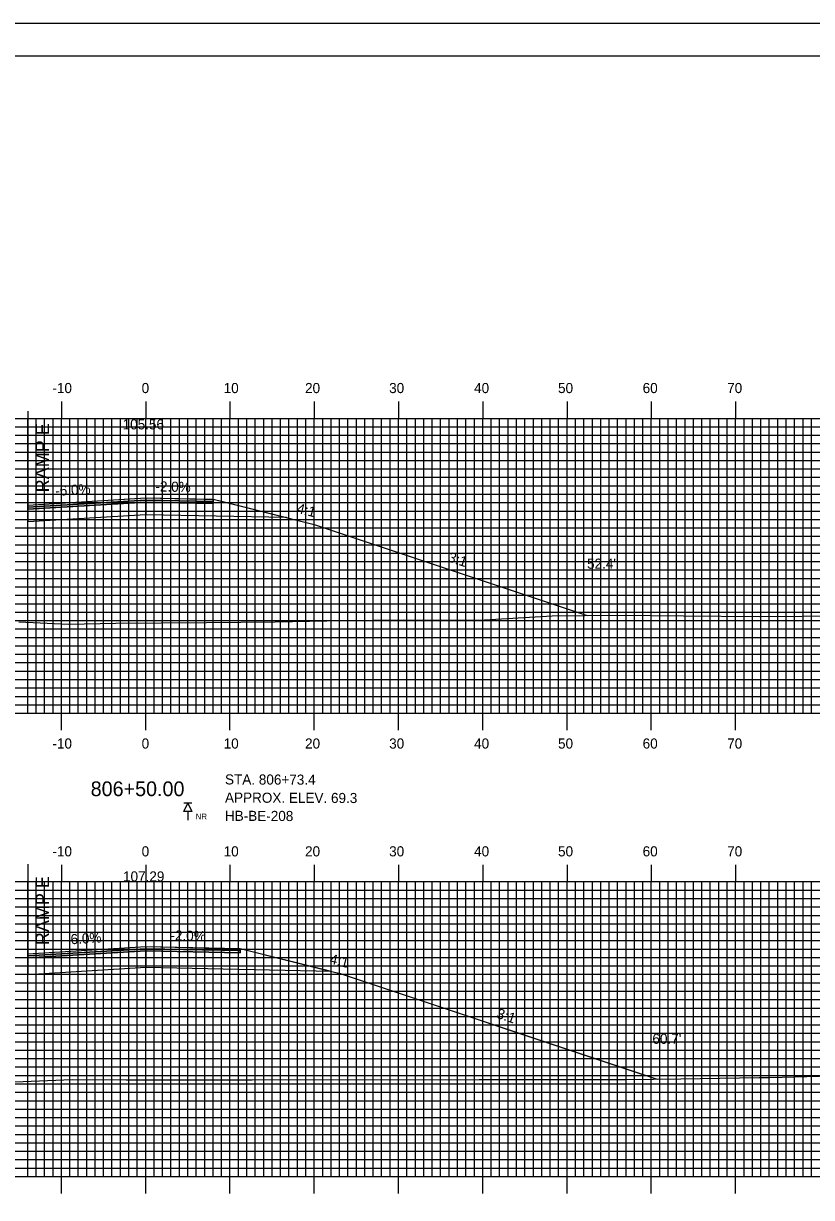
# Model space of a CAD drawing. Extents: x 879 to 1222, y -1658 to -1438.
# Drawn here: x 1030.1 to 1123.7, y -1577.1 to -1437.7 of the extents above; entities that cross this region are included whole.
import ezdxf

# ---------------------------------------------------------------- set-up
doc = ezdxf.new("R2010")
doc.units = 0
for name, color, linetype in [('ANNOTATION', 7, 'Continuous'), ('BORDER', 7, 'Continuous'), ('BORING - NO REFUSAL', 7, 'Continuous'), ('D_Roadway_Centerline', 7, 'Continuous'), ('D_Roadway_Centerline_Text', 7, 'Continuous'), ('D_Roadway_Edge_Shoulder', 7, 'Continuous'), ('D_Roadway_Edge_TW', 7, 'Continuous'), ('D_Roadway_Pavement', 7, 'Continuous'), ('D_Roadway_SlopeLines', 7, 'Continuous'), ('D_Roadway_SubGrade', 7, 'Continuous'), ('D_Text_Standard', 7, 'Continuous'), ('Default', 7, 'Continuous'), ('H_V ANNOTATION', 7, 'Continuous'), ('MAJOR', 7, 'Continuous'), ('MINOR', 7, 'Continuous'), ('PLOT BOUNDARY', 7, 'Continuous'), ('S_Roadway_Centerline', 7, 'Continuous')]:
    doc.layers.add(name, color=color, linetype=linetype)

msp = doc.modelspace()

# ---------------------------------------------------------------- linework, layer by layer
at = {"layer": 'BORDER'}
msp.add_lwpolyline([(895.05, -1651.6), (1215.05, -1651.6), (1215.05, -1441.6), (895.05, -1441.6)], close=True, dxfattribs=at)
at = {"layer": 'BORING - NO REFUSAL'}
for p, q in [((1050.13, -1530.3), (1049.17, -1530.3)), ((1049.65, -1531.26), (1049.65, -1532.32))]:
    msp.add_line(p, q, dxfattribs=at)
msp.add_lwpolyline([(1049.65, -1530.3), (1050.13, -1531.26), (1049.17, -1531.26)], close=True, dxfattribs=at)
at = {"layer": 'D_Roadway_Centerline'}
for points in [[(1030.65, -1494.89), (1042.71, -1494.16), (1044.65, -1494.05), (1051.56, -1494.18), (1052.65, -1494.21), (1053.79, -1494.49), (1061.34, -1496.38), (1061.78, -1496.49), (1064.65, -1497.21), (1068.66, -1498.54), (1097.02, -1508)], [(1030.65, -1548.15), (1044.65, -1547.31), (1055.12, -1547.52), (1055.84, -1547.54), (1066.02, -1550.08), (1066.7, -1550.25), (1067.77, -1550.52), (1067.84, -1550.54), (1102.83, -1562.2), (1105.36, -1563.04)]]:
    msp.add_lwpolyline(points, dxfattribs=at)
at = {"layer": 'D_Roadway_Edge_Shoulder'}
for points in [[(1044.65, -1494.05), (1052.65, -1494.21), (1052.65, -1494.46), (1044.65, -1494.3)], [(1044.65, -1547.31), (1055.84, -1547.54), (1055.84, -1547.79), (1044.65, -1547.56)]]:
    msp.add_lwpolyline(points, close=True, dxfattribs=at)
at = {"layer": 'D_Roadway_Edge_TW'}
for points in [[(1030.65, -1494.89), (1044.65, -1494.05), (1044.65, -1494.3), (1030.65, -1495.14)], [(1030.65, -1548.15), (1044.65, -1547.31), (1044.65, -1547.56), (1030.65, -1548.4)]]:
    msp.add_lwpolyline(points, close=True, dxfattribs=at)
at = {"layer": 'D_Roadway_Pavement'}
for points in [[(1030.65, -1495.14), (1044.65, -1494.3), (1044.65, -1494.55), (1030.65, -1495.39)], [(1044.65, -1494.3), (1052.65, -1494.46), (1052.65, -1494.71), (1044.65, -1494.55)], [(1030.65, -1548.4), (1044.65, -1547.56), (1044.65, -1547.81), (1030.65, -1548.65)], [(1044.65, -1547.56), (1055.84, -1547.79), (1055.84, -1548.04), (1044.65, -1547.81)]]:
    msp.add_lwpolyline(points, close=True, dxfattribs=at)
for points in [[(1044.65, -1494.3), (1044.65, -1494.55)], [(1044.65, -1494.3), (1044.65, -1494.55)], [(1044.65, -1494.3), (1044.65, -1494.55)], [(1044.65, -1547.56), (1044.65, -1547.81)], [(1044.65, -1547.56), (1044.65, -1547.81)], [(1044.65, -1547.56), (1044.65, -1547.81)]]:
    msp.add_lwpolyline(points, dxfattribs=at)
at = {"layer": 'D_Roadway_SlopeLines'}
for points in [[(1052.65, -1494.21), (1064.65, -1497.21), (1097.02, -1508)], [(1052.65, -1494.21), (1064.65, -1497.21), (1097.02, -1508)], [(1055.84, -1547.54), (1067.84, -1550.54), (1105.36, -1563.04)], [(1055.84, -1547.54), (1067.84, -1550.54), (1105.36, -1563.04)]]:
    msp.add_lwpolyline(points, dxfattribs=at)
at = {"layer": 'D_Roadway_SubGrade'}
for p, q in [((1030.65, -1483.75), (1030.65, -1496.89)), ((1030.65, -1537.51), (1030.65, -1550.65))]:
    msp.add_line(p, q, dxfattribs=at)
for points in [[(1030.65, -1495.39), (1044.65, -1494.55), (1044.65, -1496.05), (1030.65, -1496.89)], [(1044.65, -1494.55), (1044.65, -1494.3), (1052.65, -1494.46), (1052.65, -1494.21), (1061.34, -1496.38), (1044.65, -1496.05)], [(1044.65, -1494.55), (1052.65, -1494.71), (1052.65, -1494.46), (1052.65, -1494.21), (1061.34, -1496.38), (1044.65, -1496.05)], [(1030.65, -1548.65), (1044.65, -1547.81), (1044.65, -1549.81), (1030.65, -1550.65)], [(1044.65, -1547.81), (1044.65, -1547.56), (1055.84, -1547.79), (1055.84, -1547.54), (1066.7, -1550.25), (1044.65, -1549.81)], [(1044.65, -1547.81), (1055.84, -1548.04), (1055.84, -1547.79), (1055.84, -1547.54), (1066.7, -1550.25), (1044.65, -1549.81)]]:
    msp.add_lwpolyline(points, close=True, dxfattribs=at)
at = {"layer": 'Default'}
msp.add_line((1030.65, -1496.89), (1030.65, -1491.77), dxfattribs=at)
at = {"layer": 'MAJOR'}
for p, q in [((1034.65, -1482.6), (1034.65, -1484.6)), ((1044.65, -1482.6), (1044.65, -1484.6)), ((1054.65, -1482.6), (1054.65, -1484.6)), ((1064.65, -1482.6), (1064.65, -1484.6)), ((1074.65, -1482.6), (1074.65, -1484.6)), ((1084.65, -1482.6), (1084.65, -1484.6)), ((1094.65, -1482.6), (1094.65, -1484.6)), ((1104.65, -1482.6), (1104.65, -1484.6)), ((1114.65, -1482.6), (1114.65, -1484.6)), ((904.65, -1484.6), (1184.65, -1484.6)), ((904.65, -1484.6), (1184.65, -1484.6)), ((1034.65, -1519.6), (1034.65, -1484.6)), ((1044.65, -1519.6), (1044.65, -1484.6)), ((1054.65, -1519.6), (1054.65, -1484.6)), ((1064.65, -1519.6), (1064.65, -1484.6)), ((1074.65, -1519.6), (1074.65, -1484.6)), ((1084.65, -1519.6), (1084.65, -1484.6)), ((1094.65, -1519.6), (1094.65, -1484.6)), ((1104.65, -1519.6), (1104.65, -1484.6)), ((1114.65, -1519.6), (1114.65, -1484.6)), ((904.65, -1489.6), (1184.65, -1489.6)), ((904.65, -1494.6), (1184.65, -1494.6)), ((904.65, -1499.6), (1184.65, -1499.6)), ((904.65, -1504.6), (1184.65, -1504.6)), ((904.65, -1509.6), (1184.65, -1509.6)), ((904.65, -1514.6), (1184.65, -1514.6)), ((904.65, -1519.6), (1184.65, -1519.6)), ((904.65, -1519.6), (1184.65, -1519.6)), ((1034.65, -1521.61), (1034.65, -1519.6)), ((1044.65, -1521.61), (1044.65, -1519.6)), ((1054.65, -1521.61), (1054.65, -1519.6)), ((1064.65, -1521.61), (1064.65, -1519.6)), ((1074.65, -1521.61), (1074.65, -1519.6)), ((1084.65, -1521.61), (1084.65, -1519.6)), ((1094.65, -1521.61), (1094.65, -1519.6)), ((1104.65, -1521.61), (1104.65, -1519.6)), ((1114.65, -1521.61), (1114.65, -1519.6)), ((1034.65, -1537.6), (1034.65, -1539.6)), ((1044.65, -1537.6), (1044.65, -1539.6)), ((1054.65, -1537.6), (1054.65, -1539.6)), ((1064.65, -1537.6), (1064.65, -1539.6)), ((1074.65, -1537.6), (1074.65, -1539.6)), ((1084.65, -1537.6), (1084.65, -1539.6)), ((1094.65, -1537.6), (1094.65, -1539.6)), ((1104.65, -1537.6), (1104.65, -1539.6)), ((1114.65, -1537.6), (1114.65, -1539.6)), ((904.65, -1539.6), (1184.65, -1539.6)), ((904.65, -1539.6), (1184.65, -1539.6)), ((1034.65, -1574.6), (1034.65, -1539.6)), ((1044.65, -1574.6), (1044.65, -1539.6)), ((1054.65, -1574.6), (1054.65, -1539.6)), ((1064.65, -1574.6), (1064.65, -1539.6)), ((1074.65, -1574.6), (1074.65, -1539.6)), ((1084.65, -1574.6), (1084.65, -1539.6)), ((1094.65, -1574.6), (1094.65, -1539.6)), ((1104.65, -1574.6), (1104.65, -1539.6)), ((1114.65, -1574.6), (1114.65, -1539.6)), ((904.65, -1544.6), (1184.65, -1544.6)), ((904.65, -1549.6), (1184.65, -1549.6)), ((904.65, -1554.6), (1184.65, -1554.6)), ((904.65, -1559.6), (1184.65, -1559.6)), ((904.65, -1564.6), (1184.65, -1564.6)), ((904.65, -1569.6), (1184.65, -1569.6)), ((904.65, -1574.6), (1184.65, -1574.6)), ((904.65, -1574.6), (1184.65, -1574.6)), ((1034.65, -1576.61), (1034.65, -1574.6)), ((1044.65, -1576.61), (1044.65, -1574.6)), ((1054.65, -1576.61), (1054.65, -1574.6)), ((1064.65, -1576.61), (1064.65, -1574.6)), ((1074.65, -1576.61), (1074.65, -1574.6)), ((1084.65, -1576.61), (1084.65, -1574.6)), ((1094.65, -1576.61), (1094.65, -1574.6)), ((1104.65, -1576.61), (1104.65, -1574.6)), ((1114.65, -1576.61), (1114.65, -1574.6))]:
    msp.add_line(p, q, dxfattribs=at)
at = {"layer": 'MINOR'}
for p, q in [((904.65, -1485.6), (1184.65, -1485.6)), ((1030.65, -1519.6), (1030.65, -1484.6)), ((1031.65, -1519.6), (1031.65, -1484.6)), ((1032.65, -1519.6), (1032.65, -1484.6)), ((1033.65, -1519.6), (1033.65, -1484.6)), ((1035.65, -1519.6), (1035.65, -1484.6)), ((1036.65, -1519.6), (1036.65, -1484.6)), ((1037.65, -1519.6), (1037.65, -1484.6)), ((1038.65, -1519.6), (1038.65, -1484.6)), ((1039.65, -1519.6), (1039.65, -1484.6)), ((1040.65, -1519.6), (1040.65, -1484.6)), ((1041.65, -1519.6), (1041.65, -1484.6)), ((1042.65, -1519.6), (1042.65, -1484.6)), ((1043.65, -1519.6), (1043.65, -1484.6)), ((1045.65, -1519.6), (1045.65, -1484.6)), ((1046.65, -1519.6), (1046.65, -1484.6)), ((1047.65, -1519.6), (1047.65, -1484.6)), ((1048.65, -1519.6), (1048.65, -1484.6)), ((1049.65, -1519.6), (1049.65, -1484.6)), ((1050.65, -1519.6), (1050.65, -1484.6)), ((1051.65, -1519.6), (1051.65, -1484.6)), ((1052.65, -1519.6), (1052.65, -1484.6)), ((1053.65, -1519.6), (1053.65, -1484.6)), ((1055.65, -1519.6), (1055.65, -1484.6)), ((1056.65, -1519.6), (1056.65, -1484.6)), ((1057.65, -1519.6), (1057.65, -1484.6)), ((1058.65, -1519.6), (1058.65, -1484.6)), ((1059.65, -1519.6), (1059.65, -1484.6)), ((1060.65, -1519.6), (1060.65, -1484.6)), ((1061.65, -1519.6), (1061.65, -1484.6)), ((1062.65, -1519.6), (1062.65, -1484.6)), ((1063.65, -1519.6), (1063.65, -1484.6)), ((1065.65, -1519.6), (1065.65, -1484.6)), ((1066.65, -1519.6), (1066.65, -1484.6)), ((1067.65, -1519.6), (1067.65, -1484.6)), ((1068.65, -1519.6), (1068.65, -1484.6)), ((1069.65, -1519.6), (1069.65, -1484.6)), ((1070.65, -1519.6), (1070.65, -1484.6)), ((1071.65, -1519.6), (1071.65, -1484.6)), ((1072.65, -1519.6), (1072.65, -1484.6)), ((1073.65, -1519.6), (1073.65, -1484.6)), ((1075.65, -1519.6), (1075.65, -1484.6)), ((1076.65, -1519.6), (1076.65, -1484.6)), ((1077.65, -1519.6), (1077.65, -1484.6)), ((1078.65, -1519.6), (1078.65, -1484.6)), ((1079.65, -1519.6), (1079.65, -1484.6)), ((1080.65, -1519.6), (1080.65, -1484.6)), ((1081.65, -1519.6), (1081.65, -1484.6)), ((1082.65, -1519.6), (1082.65, -1484.6)), ((1083.65, -1519.6), (1083.65, -1484.6)), ((1085.65, -1519.6), (1085.65, -1484.6)), ((1086.65, -1519.6), (1086.65, -1484.6)), ((1087.65, -1519.6), (1087.65, -1484.6)), ((1088.65, -1519.6), (1088.65, -1484.6)), ((1089.65, -1519.6), (1089.65, -1484.6)), ((1090.65, -1519.6), (1090.65, -1484.6)), ((1091.65, -1519.6), (1091.65, -1484.6)), ((1092.65, -1519.6), (1092.65, -1484.6)), ((1093.65, -1519.6), (1093.65, -1484.6)), ((1095.65, -1519.6), (1095.65, -1484.6)), ((1096.65, -1519.6), (1096.65, -1484.6)), ((1097.65, -1519.6), (1097.65, -1484.6)), ((1098.65, -1519.6), (1098.65, -1484.6)), ((1099.65, -1519.6), (1099.65, -1484.6)), ((1100.65, -1519.6), (1100.65, -1484.6)), ((1101.65, -1519.6), (1101.65, -1484.6)), ((1102.65, -1519.6), (1102.65, -1484.6)), ((1103.65, -1519.6), (1103.65, -1484.6)), ((1105.65, -1519.6), (1105.65, -1484.6)), ((1106.65, -1519.6), (1106.65, -1484.6)), ((1107.65, -1519.6), (1107.65, -1484.6)), ((1108.65, -1519.6), (1108.65, -1484.6)), ((1109.65, -1519.6), (1109.65, -1484.6)), ((1110.65, -1519.6), (1110.65, -1484.6)), ((1111.65, -1519.6), (1111.65, -1484.6)), ((1112.65, -1519.6), (1112.65, -1484.6)), ((1113.65, -1519.6), (1113.65, -1484.6)), ((1115.65, -1519.6), (1115.65, -1484.6)), ((1116.65, -1519.6), (1116.65, -1484.6)), ((1117.65, -1519.6), (1117.65, -1484.6)), ((1118.65, -1519.6), (1118.65, -1484.6)), ((1119.65, -1519.6), (1119.65, -1484.6)), ((1120.65, -1519.6), (1120.65, -1484.6)), ((1121.65, -1519.6), (1121.65, -1484.6)), ((1122.65, -1519.6), (1122.65, -1484.6)), ((1123.65, -1519.6), (1123.65, -1484.6)), ((904.65, -1486.6), (1184.65, -1486.6)), ((904.65, -1487.6), (1184.65, -1487.6)), ((904.65, -1488.6), (1184.65, -1488.6)), ((904.65, -1490.6), (1184.65, -1490.6)), ((904.65, -1491.6), (1184.65, -1491.6)), ((904.65, -1492.6), (1184.65, -1492.6)), ((904.65, -1493.6), (1184.65, -1493.6)), ((904.65, -1495.6), (1184.65, -1495.6)), ((904.65, -1496.6), (1184.65, -1496.6)), ((904.65, -1497.6), (1184.65, -1497.6)), ((904.65, -1498.6), (1184.65, -1498.6)), ((904.65, -1500.6), (1184.65, -1500.6)), ((904.65, -1501.6), (1184.65, -1501.6)), ((904.65, -1502.6), (1184.65, -1502.6)), ((904.65, -1503.6), (1184.65, -1503.6)), ((904.65, -1505.6), (1184.65, -1505.6)), ((904.65, -1506.6), (1184.65, -1506.6)), ((904.65, -1507.6), (1184.65, -1507.6)), ((904.65, -1508.6), (1184.65, -1508.6)), ((904.65, -1510.6), (1184.65, -1510.6)), ((904.65, -1511.6), (1184.65, -1511.6)), ((904.65, -1512.6), (1184.65, -1512.6)), ((904.65, -1513.6), (1184.65, -1513.6)), ((904.65, -1515.6), (1184.65, -1515.6)), ((904.65, -1516.6), (1184.65, -1516.6)), ((904.65, -1517.6), (1184.65, -1517.6)), ((904.65, -1518.6), (1184.65, -1518.6)), ((1030.65, -1574.6), (1030.65, -1539.6)), ((1031.65, -1574.6), (1031.65, -1539.6)), ((1032.65, -1574.6), (1032.65, -1539.6)), ((1033.65, -1574.6), (1033.65, -1539.6)), ((1035.65, -1574.6), (1035.65, -1539.6)), ((1036.65, -1574.6), (1036.65, -1539.6)), ((1037.65, -1574.6), (1037.65, -1539.6)), ((1038.65, -1574.6), (1038.65, -1539.6)), ((1039.65, -1574.6), (1039.65, -1539.6)), ((1040.65, -1574.6), (1040.65, -1539.6)), ((1041.65, -1574.6), (1041.65, -1539.6)), ((1042.65, -1574.6), (1042.65, -1539.6)), ((1043.65, -1574.6), (1043.65, -1539.6)), ((1045.65, -1574.6), (1045.65, -1539.6)), ((1046.65, -1574.6), (1046.65, -1539.6)), ((1047.65, -1574.6), (1047.65, -1539.6)), ((1048.65, -1574.6), (1048.65, -1539.6)), ((1049.65, -1574.6), (1049.65, -1539.6)), ((1050.65, -1574.6), (1050.65, -1539.6)), ((1051.65, -1574.6), (1051.65, -1539.6)), ((1052.65, -1574.6), (1052.65, -1539.6)), ((1053.65, -1574.6), (1053.65, -1539.6)), ((1055.65, -1574.6), (1055.65, -1539.6)), ((1056.65, -1574.6), (1056.65, -1539.6)), ((1057.65, -1574.6), (1057.65, -1539.6)), ((1058.65, -1574.6), (1058.65, -1539.6)), ((1059.65, -1574.6), (1059.65, -1539.6)), ((1060.65, -1574.6), (1060.65, -1539.6)), ((1061.65, -1574.6), (1061.65, -1539.6)), ((1062.65, -1574.6), (1062.65, -1539.6)), ((1063.65, -1574.6), (1063.65, -1539.6)), ((1065.65, -1574.6), (1065.65, -1539.6)), ((1066.65, -1574.6), (1066.65, -1539.6)), ((1067.65, -1574.6), (1067.65, -1539.6)), ((1068.65, -1574.6), (1068.65, -1539.6)), ((1069.65, -1574.6), (1069.65, -1539.6)), ((1070.65, -1574.6), (1070.65, -1539.6)), ((1071.65, -1574.6), (1071.65, -1539.6)), ((1072.65, -1574.6), (1072.65, -1539.6)), ((1073.65, -1574.6), (1073.65, -1539.6)), ((1075.65, -1574.6), (1075.65, -1539.6)), ((1076.65, -1574.6), (1076.65, -1539.6)), ((1077.65, -1574.6), (1077.65, -1539.6)), ((1078.65, -1574.6), (1078.65, -1539.6)), ((1079.65, -1574.6), (1079.65, -1539.6)), ((1080.65, -1574.6), (1080.65, -1539.6)), ((1081.65, -1574.6), (1081.65, -1539.6)), ((1082.65, -1574.6), (1082.65, -1539.6)), ((1083.65, -1574.6), (1083.65, -1539.6)), ((1085.65, -1574.6), (1085.65, -1539.6)), ((1086.65, -1574.6), (1086.65, -1539.6)), ((1087.65, -1574.6), (1087.65, -1539.6)), ((1088.65, -1574.6), (1088.65, -1539.6)), ((1089.65, -1574.6), (1089.65, -1539.6)), ((1090.65, -1574.6), (1090.65, -1539.6)), ((1091.65, -1574.6), (1091.65, -1539.6)), ((1092.65, -1574.6), (1092.65, -1539.6)), ((1093.65, -1574.6), (1093.65, -1539.6)), ((1095.65, -1574.6), (1095.65, -1539.6)), ((1096.65, -1574.6), (1096.65, -1539.6)), ((1097.65, -1574.6), (1097.65, -1539.6)), ((1098.65, -1574.6), (1098.65, -1539.6)), ((1099.65, -1574.6), (1099.65, -1539.6)), ((1100.65, -1574.6), (1100.65, -1539.6)), ((1101.65, -1574.6), (1101.65, -1539.6)), ((1102.65, -1574.6), (1102.65, -1539.6)), ((1103.65, -1574.6), (1103.65, -1539.6)), ((1105.65, -1574.6), (1105.65, -1539.6)), ((1106.65, -1574.6), (1106.65, -1539.6)), ((1107.65, -1574.6), (1107.65, -1539.6)), ((1108.65, -1574.6), (1108.65, -1539.6)), ((1109.65, -1574.6), (1109.65, -1539.6)), ((1110.65, -1574.6), (1110.65, -1539.6)), ((1111.65, -1574.6), (1111.65, -1539.6)), ((1112.65, -1574.6), (1112.65, -1539.6)), ((1113.65, -1574.6), (1113.65, -1539.6)), ((1115.65, -1574.6), (1115.65, -1539.6)), ((1116.65, -1574.6), (1116.65, -1539.6)), ((1117.65, -1574.6), (1117.65, -1539.6)), ((1118.65, -1574.6), (1118.65, -1539.6)), ((1119.65, -1574.6), (1119.65, -1539.6)), ((1120.65, -1574.6), (1120.65, -1539.6)), ((1121.65, -1574.6), (1121.65, -1539.6)), ((1122.65, -1574.6), (1122.65, -1539.6)), ((1123.65, -1574.6), (1123.65, -1539.6)), ((904.65, -1540.6), (1184.65, -1540.6)), ((904.65, -1541.6), (1184.65, -1541.6)), ((904.65, -1542.6), (1184.65, -1542.6)), ((904.65, -1543.6), (1184.65, -1543.6)), ((904.65, -1545.6), (1184.65, -1545.6)), ((904.65, -1546.6), (1184.65, -1546.6)), ((904.65, -1547.6), (1184.65, -1547.6)), ((904.65, -1548.6), (1184.65, -1548.6)), ((904.65, -1550.6), (1184.65, -1550.6)), ((904.65, -1551.6), (1184.65, -1551.6)), ((904.65, -1552.6), (1184.65, -1552.6)), ((904.65, -1553.6), (1184.65, -1553.6)), ((904.65, -1555.6), (1184.65, -1555.6)), ((904.65, -1556.6), (1184.65, -1556.6)), ((904.65, -1557.6), (1184.65, -1557.6)), ((904.65, -1558.6), (1184.65, -1558.6)), ((904.65, -1560.6), (1184.65, -1560.6)), ((904.65, -1561.6), (1184.65, -1561.6)), ((904.65, -1562.6), (1184.65, -1562.6)), ((904.65, -1563.6), (1184.65, -1563.6)), ((904.65, -1565.6), (1184.65, -1565.6)), ((904.65, -1566.6), (1184.65, -1566.6)), ((904.65, -1567.6), (1184.65, -1567.6)), ((904.65, -1568.6), (1184.65, -1568.6)), ((904.65, -1570.6), (1184.65, -1570.6)), ((904.65, -1571.6), (1184.65, -1571.6)), ((904.65, -1572.6), (1184.65, -1572.6)), ((904.65, -1573.6), (1184.65, -1573.6))]:
    msp.add_line(p, q, dxfattribs=at)
at = {"layer": 'PLOT BOUNDARY'}
msp.add_lwpolyline([(878.86, -1657.72), (1218.86, -1657.72), (1218.86, -1437.72), (878.86, -1437.72)], close=True, dxfattribs=at)
at = {"layer": 'S_Roadway_Centerline'}
for points in [[(1029.58, -1508.74), (1035.48, -1509.02), (1041.11, -1508.92), (1051.86, -1508.83), (1060.02, -1508.77), (1068.21, -1508.6), (1075.2, -1508.53), (1084.19, -1508.54), (1092.9, -1508.03), (1100.62, -1507.97), (1108.45, -1508.03), (1117.43, -1508.14), (1127.6, -1508.04), (1133.42, -1507.76), (1144.55, -1507.77), (1150.5, -1507.75), (1162.89, -1507.6), (1167.05, -1507.63), (1171.39, -1507.76), (1183.39, -1508.09), (1184.65, -1508.08)], [(1029.13, -1563.37), (1035.94, -1563.09), (1042.32, -1563.11), (1053.45, -1563.11), (1057.29, -1563.12), (1084.22, -1563.09), (1086.31, -1563.07), (1088.39, -1563.09), (1101.66, -1563.1), (1108.17, -1563), (1117.46, -1562.86), (1118.73, -1562.85), (1134.78, -1562.43), (1135.95, -1562.41), (1137.31, -1562.42), (1152.94, -1562.84), (1156.79, -1562.81), (1168.28, -1562.55), (1174.99, -1562.68), (1184.65, -1562.88)]]:
    msp.add_lwpolyline(points, dxfattribs=at)

# ---------------------------------------------------------------- texts
at = {"layer": 'ANNOTATION'}
for s, height, rotation, p in [('RAMP E', 1.6, 90, (1033.18, -1493.38)), ('-6.0%', 1.2, 3.4336, (1033.95, -1493.81)), ('-2.0%', 1.2, 358.8535, (1045.79, -1493.27)), ('4:1', 1.2, 345.9637, (1062.5, -1495.81)), ('3:1', 1.2, 341.5652, (1080.44, -1501.56)), ('RAMP E', 1.6, 90, (1033.18, -1547.14)), ('-6.0%', 1.2, 3.434, (1035.24, -1547.07)), ('-2.0%', 1.2, 358.8546, (1047.57, -1546.57)), ('4:1', 1.2, 345.9604, (1066.4, -1549.31)), ('3:1', 1.2, 341.5652, (1086.2, -1555.75))]:
    msp.add_text(s, height=height, rotation=rotation, dxfattribs=at).set_placement(p)
at = {"layer": 'BORING - NO REFUSAL'}
for s, p in [('STA. 806+73.4', (1054.06, -1528.06)), ('APPROX. ELEV. 69.3', (1054.06, -1530.22)), ('HB-BE-208', (1054.05, -1532.38))]:
    msp.add_text(s, height=1.2, rotation=359.8142, dxfattribs=at).set_placement(p)
msp.add_text('NR', height=0.7, dxfattribs=at).set_placement((1050.58, -1532.22))
at = {"layer": 'D_Roadway_Centerline_Text'}
for s, p in [('105.56', (1041.91, -1485.91)), ('107.29', (1041.96, -1539.58))]:
    msp.add_text(s, height=1.2, dxfattribs=at).set_placement(p)
at = {"layer": 'D_Text_Standard'}
for s, p in [("52.4'", (1097.02, -1502.45)), ("60.7'", (1104.78, -1558.85))]:
    msp.add_text(s, height=1.2, dxfattribs=at).set_placement(p)
at = {"layer": 'H_V ANNOTATION'}
for s, height, p in [('-10', 1.2, (1033.58, -1481.6)), ('0', 1.2, (1044.17, -1481.6)), ('10', 1.2, (1053.9, -1481.6)), ('20', 1.2, (1063.56, -1481.6)), ('30', 1.2, (1073.54, -1481.6)), ('40', 1.2, (1083.62, -1481.6)), ('50', 1.2, (1093.58, -1481.6)), ('60', 1.2, (1103.62, -1481.6)), ('70', 1.2, (1113.65, -1481.6)), ('-10', 1.2, (1033.58, -1523.8)), ('0', 1.2, (1044.17, -1523.8)), ('10', 1.2, (1053.9, -1523.8)), ('20', 1.2, (1063.56, -1523.8)), ('30', 1.2, (1073.54, -1523.8)), ('40', 1.2, (1083.62, -1523.8)), ('50', 1.2, (1093.58, -1523.8)), ('60', 1.2, (1103.62, -1523.8)), ('70', 1.2, (1113.65, -1523.8)), ('806+50.00', 1.75, (1038.12, -1529.45)), ('-10', 1.2, (1033.58, -1536.6)), ('0', 1.2, (1044.17, -1536.6)), ('10', 1.2, (1053.9, -1536.6)), ('20', 1.2, (1063.56, -1536.6)), ('30', 1.2, (1073.54, -1536.6)), ('40', 1.2, (1083.62, -1536.6)), ('50', 1.2, (1093.58, -1536.6)), ('60', 1.2, (1103.62, -1536.6)), ('70', 1.2, (1113.65, -1536.6))]:
    msp.add_text(s, height=height, dxfattribs=at).set_placement(p)

doc.saveas('drawing.dxf')
